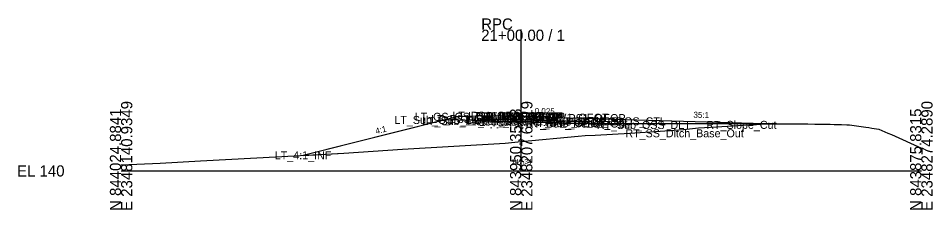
# Model space of a CAD drawing. Extents: x -26 to 203, y -10 to 7538.
# Drawn here: x -25.7 to 202.8, y 7490.3 to 7538.2 of the extents above; entities that cross this region are included whole.
import ezdxf

# ---------------------------------------------------------------- set-up
doc = ezdxf.new("R2010")
doc.units = 0
for name, color, linetype in [('Default', 7, 'Continuous'), ('Exist Cross Section Cell', 7, 'Continuous'), ('Exist XS Center Line Elevation Label', 7, 'Continuous'), ('Exist XS Ground Line', 7, 'Continuous'), ('Prop CMT Pvmt Course 1', 7, 'Continuous'), ('Prop CMT Pvmt Course 2', 7, 'Continuous'), ('Prop CMT Pvmt Course 3', 7, 'Continuous'), ('Prop CMT Pvmt Surface', 7, 'Continuous'), ('Prop CMT Pvmt Surface Shoulder', 7, 'Continuous'), ('Prop CMT Shld Paved Course 1', 7, 'Continuous'), ('Prop CMT Shld Paved Course 2', 7, 'Continuous'), ('Prop CMT Shld Paved Course 3', 7, 'Continuous'), ('Prop CMT Slope Grass', 7, 'Continuous'), ('Prop CMT Subgrade Earthwork', 7, 'Continuous'), ('Prop XS Earthwork Shape', 7, 'Continuous'), ('Prop XS SE Text', 7, 'Continuous'), ('Prop XS Side Slope Text', 7, 'Continuous'), ('Scratch_Level_0', 7, 'Continuous')]:
    doc.layers.add(name, color=color, linetype=linetype)

msp = doc.modelspace()

# ---------------------------------------------------------------- linework, layer by layer
at = {"layer": 'Exist Cross Section Cell'}
for p, q in [((100, 7500), (100, 7535.32)), ((0, 7500), (100, 7500)), ((100, 7500), (200, 7500))]:
    msp.add_line(p, q, dxfattribs=at)
at = {"layer": 'Exist XS Ground Line'}
msp.add_lwpolyline([(0, 7501.49), (9.75, 7501.93), (19.88, 7502.56), (33.9, 7503.3), (55.68, 7504.43), (70.34, 7505.46), (96.01, 7506.96), (100, 7507.34), (114.22, 7508.68), (115.98, 7508.83), (118.52, 7508.94), (127.13, 7509.43), (133.52, 7509.85), (140.54, 7510.39), (144.31, 7510.76), (148.8, 7511.04), (158.3, 7511.62), (158.81, 7511.64), (159.95, 7511.72), (160.4, 7511.74), (161.77, 7511.77), (163.76, 7511.77), (165.46, 7511.77), (166.65, 7511.77), (167.26, 7511.77), (167.92, 7511.77), (169.03, 7511.76), (170.02, 7511.75), (171.66, 7511.74), (173.36, 7511.72), (175.35, 7511.69), (176.68, 7511.67), (177.19, 7511.66), (178.25, 7511.65), (179.13, 7511.63), (180.03, 7511.61), (181.36, 7511.56), (182.06, 7511.54), (186.1, 7510.93), (186.87, 7510.82), (187.61, 7510.7), (189.38, 7510.43), (191.65, 7509.46), (192.51, 7509.08), (200, 7505.67)], dxfattribs=at)
at = {"layer": 'Prop CMT Pvmt Course 1'}
for p, q in [((100, 7513.61), (96, 7513.71)), ((96, 7513.71), (96, 7512.87)), ((96, 7512.87), (100, 7512.77)), ((100, 7512.77), (100, 7513.61)), ((100, 7513.61), (100, 7513.61)), ((100, 7513.61), (100, 7512.77)), ((100, 7512.77), (100, 7513.61)), ((100, 7513.61), (112, 7513.31)), ((100, 7512.77), (100, 7513.61)), ((100, 7513.61), (100, 7513.61)), ((100, 7513.61), (100, 7512.77)), ((100, 7512.77), (100, 7513.61)), ((100, 7512.77), (100, 7512.77)), ((112, 7512.47), (100, 7512.77)), ((100, 7512.77), (100, 7512.77)), ((112, 7513.31), (112, 7512.47))]:
    msp.add_line(p, q, dxfattribs=at)
at = {"layer": 'Prop CMT Pvmt Course 2'}
for p, q in [((96, 7512.87), (100, 7512.77)), ((100, 7512.77), (96, 7512.87)), ((96, 7512.87), (96, 7512.87)), ((100, 7512.77), (100, 7512.77)), ((112, 7512.47), (100, 7512.77)), ((100, 7512.77), (100, 7512.77)), ((100, 7512.77), (112, 7512.47)), ((112, 7512.47), (112, 7512.47))]:
    msp.add_line(p, q, dxfattribs=at)
at = {"layer": 'Prop CMT Pvmt Course 3'}
for p, q in [((100, 7512.77), (96, 7512.87)), ((96, 7512.87), (96, 7512.37)), ((96, 7512.37), (100, 7512.27)), ((100, 7512.27), (100, 7512.77)), ((100, 7512.77), (112, 7512.47)), ((100, 7512.27), (100, 7512.77)), ((112, 7511.97), (100, 7512.27)), ((112, 7512.47), (112, 7511.97))]:
    msp.add_line(p, q, dxfattribs=at)
at = {"layer": 'Prop CMT Pvmt Surface'}
for q in [(96, 7513.71), (112, 7513.31)]:
    msp.add_line((100, 7513.61), q, dxfattribs=at)
at = {"layer": 'Prop CMT Pvmt Surface Shoulder'}
for p, q in [((96, 7513.71), (92, 7513.81)), ((112, 7513.31), (116, 7513.21))]:
    msp.add_line(p, q, dxfattribs=at)
at = {"layer": 'Prop CMT Shld Paved Course 1'}
for p, q in [((96, 7513.71), (92, 7513.81)), ((92, 7513.81), (92, 7512.97)), ((92, 7512.97), (96, 7512.87)), ((96, 7512.87), (96, 7513.71)), ((112, 7513.31), (116, 7513.21)), ((112, 7512.47), (112, 7513.31)), ((116, 7512.37), (112, 7512.47)), ((116, 7513.21), (116, 7512.37))]:
    msp.add_line(p, q, dxfattribs=at)
at = {"layer": 'Prop CMT Shld Paved Course 2'}
for p, q in [((96, 7512.87), (92, 7512.97)), ((92, 7512.97), (92, 7512.97)), ((92, 7512.97), (96, 7512.87)), ((96, 7512.87), (96, 7512.87)), ((112, 7512.47), (116, 7512.37)), ((116, 7512.37), (112, 7512.47)), ((112, 7512.47), (112, 7512.47)), ((116, 7512.37), (116, 7512.37))]:
    msp.add_line(p, q, dxfattribs=at)
at = {"layer": 'Prop CMT Shld Paved Course 3'}
for p, q in [((91.5, 7512.99), (91.01, 7512.5)), ((91.01, 7512.5), (96, 7512.37)), ((92, 7512.97), (91.5, 7512.99)), ((96, 7512.87), (92, 7512.97)), ((96, 7512.37), (96, 7512.87)), ((112, 7512.47), (116, 7512.37)), ((112, 7511.97), (112, 7512.47)), ((117.01, 7511.85), (112, 7511.97)), ((116, 7512.37), (116.5, 7512.36)), ((116.5, 7512.36), (117.01, 7511.85))]:
    msp.add_line(p, q, dxfattribs=at)
at = {"layer": 'Prop CMT Slope Grass'}
for p, q in [((84, 7513.53), (45.48, 7503.9)), ((92, 7513.81), (84, 7513.53)), ((116, 7513.21), (126, 7512.86)), ((126, 7512.86), (163.76, 7511.77))]:
    msp.add_line(p, q, dxfattribs=at)
at = {"layer": 'Prop CMT Subgrade Earthwork'}
for p, q in [((91.01, 7512.5), (80.9, 7512.75)), ((96, 7512.37), (91.01, 7512.5)), ((100, 7512.27), (96, 7512.37)), ((100, 7512.27), (112, 7511.97)), ((112, 7511.97), (117.01, 7511.85)), ((117.01, 7511.85), (163.76, 7511.77))]:
    msp.add_line(p, q, dxfattribs=at)
at = {"layer": 'Prop XS Earthwork Shape'}
msp.add_lwpolyline([(55.68, 7504.43), (70.34, 7505.46), (96.01, 7506.96), (100, 7507.34), (114.22, 7508.68), (115.98, 7508.83), (118.52, 7508.94), (127.13, 7509.43), (133.52, 7509.85), (140.54, 7510.39), (144.31, 7510.76), (148.8, 7511.04), (158.3, 7511.62), (158.81, 7511.64), (159.95, 7511.72), (160.4, 7511.74), (161.77, 7511.77), (163.76, 7511.77), (117.01, 7511.85), (112, 7511.97), (100, 7512.27), (96, 7512.37), (91.01, 7512.5), (80.9, 7512.75), (45.48, 7503.9)], close=True, dxfattribs=at)

# ---------------------------------------------------------------- texts
at = {"layer": 'Default'}
msp.add_text('-', height=0.0001, dxfattribs=at).set_placement((0, 7500))
at = {"layer": 'Exist Cross Section Cell'}
for s, p in [('RPC', (90, 7535.32)), ('21+00.00 / 1', (90, 7532.52)), ('EL 140', (-26, 7498.6))]:
    msp.add_text(s, height=2.8, dxfattribs=at).set_placement(p)
for s, p in [('E 2348140.9349', (2.8, 7490)), ('E 2348207.6119', (102.8, 7490)), ('E 2348274.2890', (202.8, 7490)), ('N 844024.8841', (0, 7490)), ('N 843950.3578', (100, 7490)), ('N 843875.8315', (200, 7490))]:
    msp.add_text(s, height=2.8, rotation=90, dxfattribs=at).set_placement(p)
at = {"layer": 'Exist XS Center Line Elevation Label'}
msp.add_text('147.34', height=1.2, dxfattribs=at).set_placement((97.55, 7501.74))
at = {"layer": 'Prop XS SE Text'}
msp.add_text('0.025', height=1.5, rotation=358.5679, dxfattribs=at).set_placement((103.34, 7514.27))
at = {"layer": 'Prop XS Side Slope Text'}
for s, rotation, p in [('35:1', 358.3526, (143.03, 7513.31)), ('4:1', 14.0362, (63.74, 7509.19))]:
    msp.add_text(s, height=1.5, rotation=rotation, dxfattribs=at).set_placement(p)
at = {"layer": 'Scratch_Level_0'}
for s, p in [('LT_GS_OS_CTL', (73.37, 7512.53)), ('LT_PS1_OEOP', (82.8, 7512.81)), ('LT_PV1_OEOT', (86.74, 7512.71)), ('RT_PV1_OEEOP', (89.83, 7512.61)), ('LT_PV1_OEEOP', (89.87, 7512.61)), ('RT_PV1_IEEOP', (90.47, 7512.61)), ('LT_PV1_IEEOP', (90.52, 7512.61)), ('PV1_PGL', (94.47, 7512.61)), ('RT_PV1_OEOT', (102.69, 7512.31)), ('RT_PS1_OEOP', (106.76, 7512.21)), ('LT_Sub_OSS_DLT', (68.3, 7511.75)), ('LT_Sub_Trench_Out', (75.22, 7511.5)), ('LT_PS3_Shelf_Out', (77.48, 7511.99)), ('LT_PS3_OEOP', (82.24, 7511.97)), ('LT_PS2_OEOP', (82.24, 7511.97)), ('LT_Sub_OEOT', (86.08, 7511.37)), ('LT_PV3_OEOT', (86.17, 7511.87)), ('LT_PV2_OEOT', (86.17, 7511.87)), ('RT_Sub_OEEOP', (89.17, 7511.27)), ('LT_Sub_OEEOP', (89.21, 7511.27)), ('RT_PV2_OEEOP', (89.26, 7511.77)), ('RT_PV3_OEEOP', (89.26, 7511.77)), ('LT_PV2_OEEOP', (89.31, 7511.77)), ('LT_PV3_OEEOP', (89.31, 7511.77)), ('RT_PV2_IEEOP', (89.91, 7511.77)), ('LT_PV2_IEEOP', (89.95, 7511.77)), ('PV2_PGL', (93.91, 7511.77)), ('RT_Sub_Trench_Out', (101.17, 7510.85)), ('RT_Sub_OEOT', (102.03, 7510.97)), ('RT_PV3_OEOT', (102.13, 7511.47)), ('RT_PV2_OEOT', (102.13, 7511.47)), ('RT_PS3_Shelf_Out', (102.44, 7511.36)), ('RT_PS3_OEOP', (106.19, 7511.37)), ('RT_PS2_OEOP', (106.19, 7511.37)), ('RT_GS_OS_CTL', (115.32, 7511.41)), ('RT_Sub_OSS_DLT', (118.88, 7510.49)), ('RT_Slope_Cut', (146.26, 7510.52)), ('RT_SS_Ditch_Base_Out', (126.03, 7508.41)), ('LT_4:1_INF', (38.41, 7502.9))]:
    msp.add_text(s, height=2, dxfattribs=at).set_placement(p)

doc.saveas('drawing.dxf')
